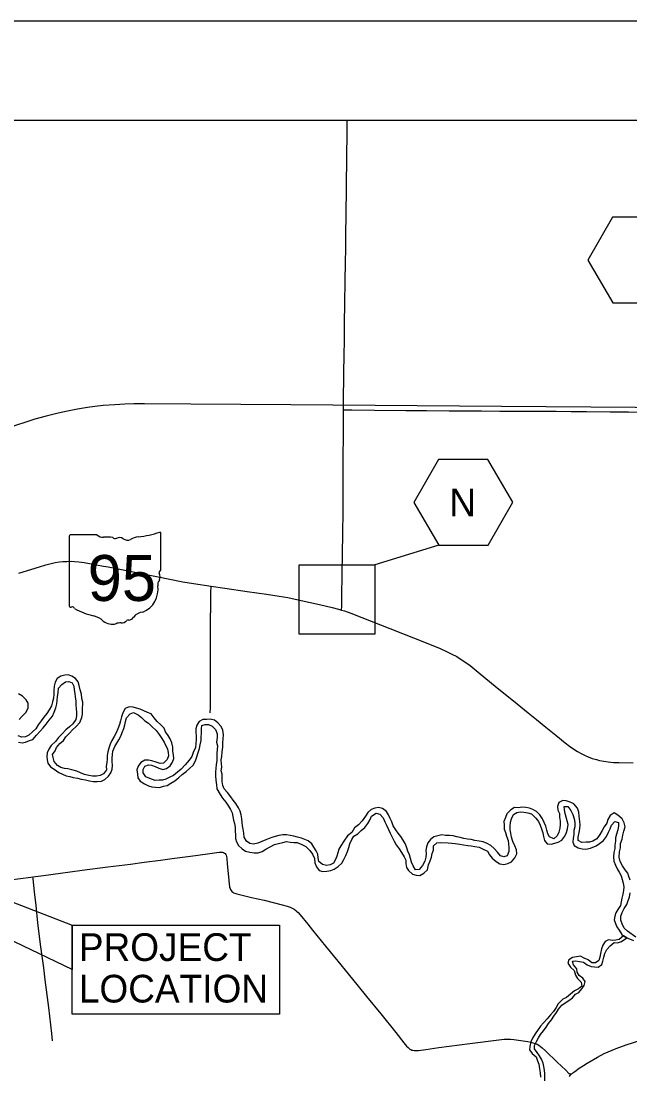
# Model space of a CAD drawing. Extents: x 0 to 680, y 0 to 440.
# Drawn here: x 128.6 to 190.2, y 333.5 to 440 of the extents above; entities that cross this region are included whole.
import ezdxf

# ---------------------------------------------------------------- set-up
doc = ezdxf.new("R2010")
doc.units = 0
for name, color, linetype in [('GM_X_County_Road', 7, 'Continuous'), ('GM_X_Major_River', 7, 'Continuous'), ('GM_X_Minor_River', 7, 'Continuous'), ('GM_X_State_Location', 7, 'Continuous'), ('GM_X_State_Route', 7, 'Continuous'), ('GM_X_State_Shield', 7, 'Continuous'), ('GM_X_Township_Road', 7, 'Continuous'), ('RD_X_RR_2', 7, 'Continuous'), ('SH_Border', 7, 'Continuous'), ('SH_Cut_Line', 7, 'Continuous'), ('SH_Text', 7, 'Continuous')]:
    doc.layers.add(name, color=color, linetype=linetype)

msp = doc.modelspace()

# ---------------------------------------------------------------- linework, layer by layer
at = {"layer": 'GM_X_County_Road'}
msp.add_line((161.21, 400.69), (161.22, 401.21), dxfattribs=at)
for points in [[(161.22, 401.21), (161.25, 404.67), (161.27, 405.98), (161.3, 407.95), (161.32, 409.48), (161.36, 411.45), (161.39, 413.74), (161.42, 415.6), (161.44, 417.02), (161.45, 418.34), (161.48, 420.52), (161.52, 423.04), (161.52, 424.02), (161.54, 425.55), (161.56, 426.43), (161.58, 428.51), (161.59, 430)], [(161.02, 380.47), (161.03, 380.85), (161.03, 381.73), (161.08, 384.24), (161.12, 386.09), (161.15, 388.27), (161.17, 390.35), (161.18, 391.55), (161.19, 396.13), (161.2, 397.88), (161.2, 399.41), (161.21, 400.39), (161.21, 400.69)], [(161.21, 400.69), (161.5, 400.69), (162.04, 400.7), (164.34, 400.67), (167.51, 400.65), (169.59, 400.64), (171.88, 400.62), (175.16, 400.6), (177.02, 400.58), (178.55, 400.57), (180.08, 400.57), (181.83, 400.56), (182.71, 400.56), (184.24, 400.53), (185.77, 400.53), (188.17, 400.5), (190.03, 400.49), (192.11, 400.48)], [(129.78, 353.5), (130.87, 353.65), (132.6, 353.88), (133.58, 354.01), (134.77, 354.17), (137.37, 354.5), (139.65, 354.79), (141.06, 354.98), (142.69, 355.19), (144.1, 355.39), (145.72, 355.6), (147.46, 355.84), (148.65, 355.98), (148.87, 355.99), (148.97, 355.98), (149.07, 355.96), (149.16, 355.91), (149.24, 355.85), (149.3, 355.77), (149.34, 355.68), (149.36, 355.57), (149.4, 355.36), (149.45, 354.82), (149.58, 353.51), (149.64, 352.75), (149.67, 352.52), (149.69, 352.41), (149.73, 352.31), (149.78, 352.21), (149.84, 352.11), (149.92, 352.03), (150.01, 351.96), (150.1, 351.9), (150.21, 351.86), (150.31, 351.82), (150.42, 351.79), (151.91, 351.43), (153.19, 351.14), (154.99, 350.68), (155.52, 350.54), (155.83, 350.43), (156.02, 350.34), (156.21, 350.24), (156.38, 350.11), (156.47, 350.04), (156.62, 349.89), (156.84, 349.65), (157.59, 348.71), (158.07, 348.11), (159.39, 346.51), (160.63, 344.98), (161.67, 343.71), (162.7, 342.44), (163.53, 341.42), (164.99, 339.64), (166.5, 337.77), (167.32, 336.74), (167.59, 336.4), (167.75, 336.24), (167.83, 336.17), (167.92, 336.1), (168.02, 336.05), (168.12, 336), (168.23, 335.97), (168.34, 335.95), (168.45, 335.94), (168.56, 335.94), (168.78, 335.96), (169.55, 336.06), (170.85, 336.25), (173.99, 336.66), (176.92, 337.04), (177.46, 337.09), (177.79, 337.1), (178.11, 337.09), (178.44, 337.05), (179.84, 336.85), (180.16, 336.79), (180.37, 336.74), (180.58, 336.67), (180.78, 336.58), (180.97, 336.48), (181.14, 336.36), (181.31, 336.22), (181.63, 335.93), (182.81, 334.78), (183.68, 333.95), (184, 333.64), (184.04, 333.62), (184.07, 333.6), (184.1, 333.58), (184.16, 333.57), (184.22, 333.58)], [(109.86, 350.92), (123.93, 352.74), (125.34, 352.93), (126.42, 353.06), (129.57, 353.47), (129.78, 353.5)], [(184.22, 333.58), (184.26, 333.59), (184.3, 333.6), (184.32, 333.62), (184.42, 333.68), (184.59, 333.82), (185.03, 334.15), (185.49, 334.45), (185.86, 334.68), (186.91, 335.27), (187.58, 335.63), (187.97, 335.83), (188.37, 336), (188.78, 336.15), (189.81, 336.51), (190.54, 336.75), (191.26, 336.99), (192.62, 337.43), (193.86, 337.84), (195.52, 338.39), (198.12, 339.25), (199.99, 339.87), (203.1, 340.9), (204.77, 341.45)], [(184.05, 333.31), (184.22, 333.58)]]:
    msp.add_lwpolyline(points, dxfattribs=at)
at = {"layer": 'GM_X_Major_River'}
for points in [[(134.83, 371.15), (134.76, 371.54), (134.71, 371.95), (134.59, 372.42), (134.48, 372.84), (134.36, 373.2), (134.1, 373.56), (133.73, 373.8), (133.35, 373.92), (133.01, 373.88), (132.63, 373.79), (132.25, 373.55), (132.05, 373.19), (131.93, 372.79), (131.9, 372.32), (131.92, 371.95), (131.89, 371.57), (131.79, 371.19), (131.67, 370.8), (131.44, 370.39), (131.2, 370.02), (130.91, 369.63), (130.62, 369.27), (130.34, 368.86), (130.1, 368.46), (129.75, 368.15), (129.37, 367.82), (129.03, 367.66), (128.67, 367.62), (128.3, 367.74)], [(128.33, 367.1), (128.7, 367.06), (129.05, 367.12), (129.44, 367.3), (129.79, 367.4), (130.16, 367.82), (130.53, 368.23), (130.82, 368.58), (131.15, 368.94), (131.45, 369.35), (131.76, 369.73), (131.96, 370.16), (132.13, 370.57), (132.21, 370.98), (132.26, 371.33), (132.28, 371.73), (132.34, 372.11), (132.37, 372.57), (132.71, 372.95), (133.09, 373.22), (133.42, 373.26), (133.77, 373.12), (133.92, 372.78), (133.96, 372.4), (134.02, 372.03), (134.07, 371.7), (134.13, 371.26), (134.15, 370.87), (134.18, 370.52), (134.2, 370.11), (134.19, 369.76), (134.15, 369.4), (133.85, 368.96), (133.5, 368.65), (133.12, 368.36), (132.75, 367.96), (132.38, 367.58), (132.08, 367.17), (131.65, 366.79), (131.39, 366.42), (131.25, 366.02), (131.2, 365.68), (131.23, 365.33), (131.31, 364.98), (131.57, 364.63), (131.93, 364.37), (132.42, 364.05), (132.78, 363.87), (133.16, 363.72), (133.53, 363.65), (133.88, 363.56), (134.31, 363.47), (134.68, 363.36), (135.12, 363.3), (135.53, 363.2), (135.89, 363.14), (136.3, 363.13)], [(128.41, 369.4), (128.72, 369.75), (129.11, 370.15), (129.3, 370.57), (129.3, 371.07), (129.11, 371.41), (128.75, 371.76), (128.33, 372.01)], [(147.71, 369.43), (147.38, 369.39), (146.98, 369.39), (146.61, 369.22), (146.37, 368.84), (146.28, 368.45), (146.29, 368.1), (146.32, 367.75), (146.3, 367.38), (146.28, 366.99), (146.24, 366.57), (146.02, 366.07), (145.88, 365.68), (145.6, 365.31), (145.19, 364.84), (144.8, 364.38), (144.43, 364.07), (144.03, 363.73), (143.64, 363.59), (143.25, 363.37), (142.89, 363.28), (142.55, 363.26), (142.15, 363.24), (141.62, 363.43), (141.21, 363.61), (140.95, 364.01), (140.94, 364.35), (141.12, 364.7), (141.47, 364.81), (141.8, 364.79), (142.17, 364.67), (142.53, 364.5), (142.92, 364.35), (143.32, 364.46), (143.68, 364.72), (143.93, 365.09), (144.04, 365.45), (144.02, 365.83), (143.96, 366.22), (143.94, 366.62), (143.83, 367.05), (143.69, 367.44), (143.48, 367.79), (143.22, 368.17), (143.08, 368.54), (142.72, 368.87), (142.36, 369.22), (142.07, 369.59), (141.75, 369.97), (141.4, 370.12), (141.02, 370.27), (140.63, 370.44), (140.28, 370.55), (139.92, 370.64), (139.52, 370.67), (139.13, 370.51), (138.89, 370.08), (138.77, 369.68), (138.64, 369.26), (138.56, 368.91), (138.37, 368.47), (138.2, 368.07), (138.01, 367.68), (137.78, 367.28), (137.62, 366.91), (137.47, 366.52), (137.37, 366.14), (137.32, 365.76), (137.31, 365.4), (137.27, 365.06), (137.22, 364.68), (137.24, 364.31), (136.93, 363.93), (136.59, 363.76), (136.22, 363.67), (135.83, 363.68), (135.44, 363.74), (135.03, 363.86), (134.62, 364.02), (134.24, 364.17), (133.72, 364.33), (133.33, 364.43), (132.99, 364.46), (132.61, 364.57), (132.27, 364.76), (131.93, 365.17), (131.83, 365.55), (131.77, 365.88), (132.03, 366.23), (132.19, 366.58), (132.52, 366.97), (132.9, 367.29), (133.12, 367.64), (133.5, 368.01), (133.81, 368.37), (134.18, 368.7), (134.54, 369.11), (134.74, 369.6), (134.8, 369.96), (134.82, 370.35), (134.83, 371.15)], [(136.3, 363.13), (136.73, 363.17), (137.07, 363.35), (137.43, 363.68), (137.69, 364.02), (137.8, 364.38), (137.85, 364.77), (137.82, 365.17), (137.82, 365.51), (137.86, 365.86), (137.89, 366.22), (138.07, 366.66), (138.27, 367.02), (138.49, 367.36), (138.7, 367.72), (138.83, 368.1), (138.99, 368.49), (139.08, 368.86), (139.16, 369.22), (139.26, 369.58), (139.63, 369.98), (139.97, 370.1), (140.43, 369.87), (140.77, 369.6), (141.11, 369.28), (141.47, 369.02), (141.84, 368.71), (142.26, 368.29), (142.56, 367.9), (142.83, 367.48), (143.08, 367.13), (143.42, 366.42), (143.49, 366.06), (143.5, 365.73), (143.39, 365.36), (143.01, 364.99), (142.67, 364.95), (142.25, 365.08), (141.82, 365.23), (141.48, 365.31), (141.13, 365.29), (140.7, 365.07), (140.43, 364.68), (140.31, 364.31), (140.39, 363.88), (140.42, 363.52), (140.65, 363.16), (141.08, 362.91), (141.49, 362.71), (141.83, 362.59), (142.21, 362.57), (142.61, 362.53), (143, 362.66), (143.36, 362.75), (143.74, 362.97), (144.14, 363.2), (144.55, 363.55), (144.9, 363.85), (145.3, 364.15), (145.64, 364.46), (145.99, 364.8), (146.24, 365.24), (146.37, 365.63), (146.51, 366.07), (146.66, 366.49), (146.72, 366.86), (146.8, 367.28), (146.8, 367.63), (146.83, 368.03), (146.84, 368.45), (146.87, 368.81), (147.22, 368.9), (147.57, 368.9), (147.91, 368.73), (148.26, 368.4), (148.42, 367.96), (148.43, 367.58), (148.37, 367.1), (148.47, 366.73), (148.42, 366.36), (148.39, 365.99), (148.4, 365.65), (148.39, 365.27), (148.32, 364.83), (148.31, 364.5), (148.27, 364.09), (148.27, 363.7), (148.29, 363.28), (148.35, 362.81), (148.4, 362.41), (148.75, 361.81), (148.96, 361.45), (149.31, 361.06), (149.57, 360.66), (149.78, 360.32), (149.95, 359.97), (150.03, 359.59), (150.1, 359.24), (150.18, 358.88), (150.24, 358.52), (150.25, 358.16)], [(169.61, 356.54), (169.55, 356.18), (169.56, 355.85), (169.52, 355.5), (169.44, 355.1), (169.2, 354.65), (168.86, 354.25), (168.49, 354.21), (168.24, 354.6), (168.09, 355), (167.99, 355.37), (167.87, 355.71), (167.72, 356.11), (167.59, 356.52), (167.44, 356.86), (167.24, 357.21), (167.01, 357.57), (166.75, 357.93), (166.51, 358.26), (166.23, 358.67), (166.09, 359.05), (165.93, 359.4), (165.76, 359.76), (165.56, 360.12), (165.16, 360.4), (164.75, 360.5), (164.39, 360.46), (164.02, 360.31), (163.66, 360.01), (163.44, 359.62), (163.1, 359.18), (162.74, 358.77), (162.32, 358.44), (162.06, 358), (161.62, 357.65), (161.25, 357.11), (160.93, 356.64), (160.75, 356.3), (160.64, 355.93), (160.52, 355.58), (160.4, 355.24), (160.21, 354.88), (159.87, 354.71), (159.5, 354.65), (159.09, 354.75), (158.73, 355.06), (158.63, 355.44), (158.6, 355.8), (158.46, 356.14), (158.22, 356.5), (157.99, 356.85), (157.64, 357.13), (157.3, 357.29), (156.95, 357.41), (156.54, 357.52), (156.2, 357.63), (155.8, 357.68), (155.45, 357.74), (155.08, 357.74), (154.68, 357.68), (154.06, 357.51), (153.68, 357.38), (153.35, 357.24), (152.96, 357.08), (152.54, 356.9), (152.1, 356.82), (151.74, 356.88), (151.4, 357.11), (151.16, 357.5), (151.13, 357.9), (151.07, 358.32), (151.01, 358.67), (150.96, 359.01), (150.93, 359.36), (150.87, 359.77), (150.75, 360.13), (150.6, 360.48), (150.31, 360.9), (150.06, 361.24), (149.8, 361.59), (149.49, 362.03), (149.13, 362.41), (148.99, 362.75), (148.93, 363.13), (148.95, 363.47), (148.93, 363.87), (148.84, 364.22), (148.91, 364.58), (148.88, 364.93), (148.85, 365.32), (148.91, 365.68), (148.95, 366.15), (149.01, 366.6), (149.01, 367.05), (149.03, 367.44), (149.06, 367.87), (149.02, 368.32), (148.85, 368.71), (148.51, 369.07), (148.16, 369.33), (147.71, 369.43)], [(189.95, 353.87), (189.71, 354.21), (189.43, 354.61), (189.19, 355.06), (189.08, 355.5), (189.12, 356.02), (189.24, 356.43), (189.24, 356.87), (189.41, 357.31), (189.45, 357.7), (189.55, 358.11), (189.68, 358.55), (189.61, 358.97), (189.39, 359.37), (188.96, 359.73), (188.57, 359.96), (188.18, 359.7), (187.96, 359.31), (187.83, 358.94), (187.58, 358.57), (187.38, 358.17), (187.12, 357.79), (186.84, 357.35), (186.44, 357.11), (186.1, 357.01), (185.74, 357.01), (185.31, 356.98), (184.93, 357.19), (184.95, 357.52), (185.05, 357.97), (185.11, 358.34), (185.13, 358.75), (185.1, 359.09), (185.05, 359.62), (185, 360.03), (184.86, 360.43), (184.5, 360.88), (184.14, 361.06), (183.73, 361.2), (183.38, 361.23), (182.99, 361.01), (182.85, 360.61), (182.9, 360.23), (183.04, 359.89), (183.05, 359.54), (183.12, 359.13), (183.11, 358.78), (183.1, 358.42), (182.98, 358.03), (182.83, 357.65), (182.49, 357.36), (182.05, 357.53), (181.88, 357.86), (181.78, 358.21), (181.66, 358.63), (181.49, 358.98), (181.32, 359.38), (181.06, 359.77), (180.72, 360.11), (180.36, 360.31), (180.02, 360.45), (179.66, 360.51), (179.27, 360.55), (178.88, 360.48), (178.51, 360.51), (178.13, 360.28), (177.73, 359.86), (177.61, 359.51), (177.42, 359.1), (177.45, 358.71), (177.46, 358.32), (177.59, 357.99), (177.68, 357.61), (177.86, 357.18), (177.9, 356.85), (177.92, 356.44), (177.94, 356.07), (177.76, 355.63), (177.43, 355.52), (177.08, 355.62), (176.8, 356.01), (176.45, 356.36), (176.1, 356.68), (175.74, 356.88), (175.32, 357.04), (174.93, 357.12), (174.5, 357.17), (174.11, 357.27), (173.76, 357.3), (173.39, 357.38), (173.01, 357.47), (172.67, 357.56), (172.31, 357.66), (171.94, 357.68), (171.54, 357.69), (171.14, 357.76), (170.75, 357.65), (170.36, 357.55), (170.01, 357.28), (169.74, 356.94), (169.61, 356.54)], [(178.21, 357.51), (178.13, 357.9), (178.05, 358.26), (178.08, 358.62), (178.11, 359.03), (178.19, 359.38), (178.39, 359.79), (178.73, 360.01), (179.09, 360.06), (179.45, 360.03), (179.85, 359.97), (180.21, 359.87), (180.67, 359.43), (180.94, 359.1), (181.1, 358.71), (181.24, 358.34), (181.38, 357.95), (181.45, 357.58), (181.53, 357.17), (181.81, 356.84), (182.21, 356.82), (182.59, 356.89), (182.93, 357), (183.29, 357.21), (183.58, 357.63), (183.78, 357.99), (183.86, 358.35), (183.93, 358.79), (183.84, 359.18), (183.74, 359.52), (183.63, 359.91), (183.55, 360.27), (183.53, 360.6), (183.91, 360.62), (184.21, 360.22), (184.41, 359.81), (184.53, 359.38), (184.59, 359), (184.59, 358.55), (184.52, 358.18), (184.5, 357.78), (184.43, 357.42), (184.39, 357.02), (184.55, 356.67), (184.96, 356.44), (185.36, 356.34), (185.73, 356.3), (186.19, 356.4), (186.76, 356.62), (187.1, 356.88), (187.49, 357.18), (187.82, 357.58), (188.01, 358.02), (188.17, 358.37), (188.33, 358.73), (188.65, 359.09), (189.02, 358.98), (189.03, 358.64), (188.95, 358.27), (188.81, 357.82), (188.73, 357.44), (188.71, 357.11), (188.65, 356.72), (188.64, 356.38), (188.54, 355.95), (188.53, 355.52), (188.54, 355.07), (188.72, 354.69), (188.89, 354.31), (189.08, 353.98), (189.28, 353.61), (189.38, 353.25), (189.49, 352.87), (189.57, 352.5), (189.52, 352.11), (189.45, 351.74), (189.37, 351.36), (189.3, 350.99), (189.24, 350.6), (188.96, 350.21), (188.75, 349.86), (188.65, 349.52), (188.58, 349.16), (188.73, 348.79), (188.87, 348.46), (189.08, 348.12), (189.35, 347.68), (189.52, 347.53)], [(150.25, 358.16), (150.28, 357.72), (150.28, 357.37), (150.39, 357.03), (150.6, 356.68), (150.97, 356.33), (151.31, 356.11), (151.72, 355.99), (152.16, 355.93), (152.59, 355.94), (152.99, 356.08), (153.37, 356.3), (153.79, 356.54), (154.23, 356.76), (154.64, 356.87), (155.08, 356.98), (155.43, 357.08), (155.8, 357.02), (156.2, 356.96), (156.53, 356.97), (156.98, 356.76), (157.41, 356.56), (157.8, 356.16), (158.09, 355.8), (158.27, 355.35), (158.3, 354.92), (158.48, 354.52), (158.74, 354.15), (159.12, 354.05), (159.53, 354.07), (159.94, 354.15), (160.28, 354.29), (160.66, 354.54), (161.04, 354.89), (161.23, 355.26), (161.46, 355.65), (161.63, 356.05), (161.76, 356.47), (161.86, 356.83), (162.05, 357.27), (162.26, 357.61), (162.66, 357.85), (163.01, 358.17), (163.35, 358.5), (163.67, 358.9), (163.89, 359.3), (164.05, 359.64), (164.5, 359.93), (164.88, 359.85), (165.22, 359.46), (165.38, 359.06), (165.55, 358.71), (165.77, 358.28), (165.92, 357.9), (166.14, 357.51), (166.35, 357.12), (166.54, 356.73), (166.83, 356.35), (167.08, 355.97), (167.34, 355.54), (167.5, 355.19), (167.51, 354.84), (167.57, 354.46), (167.77, 354.13), (168.2, 353.78), (168.57, 353.68), (168.93, 353.65), (169.34, 353.86), (169.69, 354.2), (169.82, 354.71), (169.96, 355.13), (170.1, 355.5), (170.17, 355.85), (170.3, 356.21), (170.32, 356.64), (170.66, 356.93), (171, 356.96), (171.79, 356.95), (172.15, 356.9), (172.51, 356.87), (172.98, 356.81), (173.35, 356.73), (173.78, 356.67), (174.12, 356.64), (174.48, 356.58), (174.92, 356.49), (175.27, 356.34), (175.77, 356.11), (175.99, 355.74), (176.25, 355.39), (176.65, 355.04), (177.03, 354.82), (177.44, 354.76), (177.83, 354.84), (178.19, 355.01), (178.55, 355.41), (178.74, 355.84), (178.71, 356.22), (178.55, 356.62), (178.35, 357.07), (178.21, 357.51)], [(190.19, 353.18), (190.08, 353.52), (189.95, 353.87)], [(190.78, 347.42), (189.93, 348.01), (189.58, 348.33), (189.4, 348.74), (189.27, 349.12), (189.25, 349.53), (189.39, 349.91), (189.6, 350.29), (189.86, 350.69), (190.01, 351.1), (190.12, 351.46), (190.2, 351.9)], [(189.52, 347.53), (189.85, 347.35)], [(189.85, 347.35), (190.15, 347.22), (190.53, 347.08)]]:
    msp.add_lwpolyline(points, dxfattribs=at)
at = {"layer": 'GM_X_Minor_River'}
for points in [[(189.52, 347.53), (189.09, 347.18), (188.74, 347.1), (188.41, 347.08), (188.01, 347.12), (187.67, 346.97), (187.45, 346.6), (187.3, 346.21), (187.2, 345.76), (187.14, 345.4), (187.03, 345.03), (186.68, 344.81), (186.32, 344.82), (185.95, 345.1), (185.56, 345.28), (185.17, 345.48), (184.78, 345.42), (184.36, 345.36), (184.01, 345.12), (183.89, 344.77), (184.17, 344.37), (184.53, 344.04), (184.68, 343.57), (184.86, 343.23), (185.23, 342.86), (185.31, 342.46), (184.97, 342.17), (184.58, 341.99), (184.18, 341.65), (183.75, 341.32), (183.4, 341.14), (182.93, 340.68), (182.71, 340.3), (182.46, 339.9), (182.13, 339.56), (181.82, 339.15), (181.45, 338.76), (181.14, 338.41), (180.89, 338.06), (180.58, 337.65), (180.33, 337.2), (180.17, 336.84), (180.07, 336.37), (180.01, 336.01), (180.29, 335.63), (180.68, 335.31), (180.84, 334.92), (180.96, 334.57), (181.02, 334.08), (181.1, 333.7), (181.14, 333.25)], [(181.56, 332.89), (181.57, 333.59), (181.54, 333.96), (181.46, 334.33), (181.41, 334.67), (181.25, 335.07), (181.03, 335.42), (180.8, 335.76), (180.52, 336.12), (180.51, 336.46), (180.72, 336.86), (180.93, 337.23), (181.13, 337.57), (181.44, 337.93), (181.71, 338.31), (181.95, 338.67), (182.25, 339.04), (182.48, 339.43), (182.75, 339.78), (182.96, 340.12), (183.28, 340.52), (183.64, 340.78), (184.01, 341), (184.36, 341.26), (184.68, 341.63), (185.01, 341.82), (185.31, 342.17), (185.56, 342.52), (185.65, 342.92), (185.4, 343.26), (185.06, 343.52), (184.85, 343.86), (184.81, 344.22), (184.47, 344.61), (184.36, 344.98), (184.71, 345.01), (185.07, 344.95), (185.48, 344.87), (185.85, 344.6), (186.25, 344.45), (186.61, 344.42), (186.98, 344.37), (187.33, 344.65), (187.44, 344.99), (187.53, 345.37), (187.65, 345.76), (187.83, 346.15), (188.17, 346.53), (188.57, 346.85), (188.93, 346.83), (189.32, 346.97), (189.85, 347.35)], [(189.85, 347.35), (189.52, 347.53)]]:
    msp.add_lwpolyline(points, dxfattribs=at)
at = {"layer": 'GM_X_State_Route'}
msp.add_line((170.84, 387.01), (164.37, 385.03), dxfattribs=at)
for points in [[(193.42, 420.19), (188.42, 420.17), (185.93, 415.83), (188.44, 411.51), (193.44, 411.53), (195.93, 415.86)], [(175.81, 395.69), (170.81, 395.67), (168.32, 391.33), (170.84, 387.01), (175.84, 387.03), (178.32, 391.37)]]:
    msp.add_lwpolyline(points, close=True, dxfattribs=at)
msp.add_lwpolyline([(128.38, 384.18), (130.47, 384.84), (131.1, 385.03), (131.63, 385.17), (132.05, 385.26), (132.48, 385.33), (132.81, 385.37), (133.24, 385.39), (133.68, 385.4), (134.01, 385.38), (134.44, 385.35), (134.98, 385.28), (135.52, 385.19), (136.92, 384.92), (137.4, 384.82), (140.78, 384.15), (143.46, 383.61), (144.97, 383.33), (146.05, 383.16), (147.81, 382.88), (149.19, 382.67), (151.46, 382.35), (153.41, 382.07), (154.71, 381.88), (155.57, 381.73), (156.64, 381.51), (158.78, 381.03), (160.06, 380.73), (160.69, 380.57), (161.02, 380.47), (161.32, 380.38), (161.94, 380.17), (163.06, 379.73), (165.91, 378.6), (169.57, 377.14), (170.99, 376.57), (171.69, 376.26), (172.18, 376.02), (172.66, 375.76), (173.12, 375.48), (173.58, 375.17), (174.01, 374.85), (175.04, 374.03), (176.56, 372.78), (178.77, 370.99), (179.88, 370.09), (180.73, 369.4), (181.66, 368.64), (182.68, 367.81), (183.62, 367.05), (184.05, 366.72), (184.5, 366.41), (184.87, 366.18), (185.26, 365.96), (185.65, 365.77), (185.95, 365.64), (186.37, 365.48), (186.79, 365.35), (187.11, 365.27), (187.54, 365.19), (187.97, 365.13), (188.52, 365.07), (189.07, 365.05), (190.49, 365.02)], dxfattribs=at)
at = {"layer": 'GM_X_State_Shield'}
for p, q in [((133.46, 387.94), (133.46, 380.89)), ((136.27, 388.06), (133.55, 388.06)), ((142.74, 384.55), (142.74, 388.23)), ((142.74, 384.55), (142.74, 384.55))]:
    msp.add_line(p, q, dxfattribs=at)
for centre, radius, start, end in [((133.57, 387.95), 0.108, 98.1301, 188.1301), ((136.92, 388.87), 1.04, 231.6195, 271.1119), ((137.26, 384.1), 3.74, 80.4867, 94.9883), ((138.11, 387.99), 0.301, 219.7921, 297.1024), ((138.55, 387.17), 0.626, 54.4667, 119.1411), ((140.69, 385.91), 1.98, 97.3462, 120.7689), ((139.44, 397.66), 9.84, 275.8445, 288.9065), ((142.64, 388.25), 0.103, 351.8621, 97.738), ((139.36, 388.29), 0.753, 233.8562, 294.8282), ((142.63, 384.53), 0.111, 289.6038, 7.7341), ((143.11, 383), 0.698, 136.8065, 186.9296), ((142.72, 384.28), 0.16, 107.944, 210.337), ((141.7, 383.81), 0.96, 340.033, 23.6496), ((139.99, 382.54), 2.46, 292.3089, 8.9858), ((133.57, 380.88), 0.108, 171.9584, 258.3066), ((133.58, 381.6), 0.828, 267.339, 280.6039), ((133.75, 380.49), 0.298, 29.7484, 93.2717), ((137.52, 386.81), 7.11, 240.4129, 257.1985), ((135.4, 377.73), 2.22, 47.1842, 75.836), ((137.81, 380.45), 1.41, 230.7004, 286.2918), ((138.73, 379.92), 0.752, 268.777, 315.5493), ((139.41, 379.24), 0.212, 65.7517, 132.6484), ((139.32, 380.21), 0.795, 282.8732, 323.2771), ((141.03, 378.91), 1.35, 94.4031, 142.5768), ((138.62, 378.01), 1.16, 85.6951, 111.2099)]:
    msp.add_arc(centre, radius, start, end, dxfattribs=at)
at = {"layer": 'GM_X_Township_Road'}
for points in [[(147.74, 370.08), (147.75, 370.62), (147.75, 371.39), (147.75, 372.71), (147.75, 373.48), (147.75, 374.57), (147.75, 375.34), (147.75, 376), (147.76, 376.87), (147.77, 378.08), (147.77, 378.52), (147.77, 378.95), (147.77, 379.28), (147.77, 379.5), (147.77, 379.72), (147.77, 380.16), (147.78, 380.27), (147.78, 380.49), (147.79, 380.6), (147.79, 380.71), (147.79, 380.82), (147.78, 381.14), (147.79, 381.8), (147.79, 382.35), (147.81, 382.74), (147.81, 382.88)], [(131.77, 336.91), (131.7, 337.67), (131.4, 340.28), (131.05, 343.1), (130.89, 344.29), (130.57, 346.68), (130.29, 348.85), (130.11, 350.59), (129.97, 352), (129.81, 353.3), (129.78, 353.5)]]:
    msp.add_lwpolyline(points, dxfattribs=at)
at = {"layer": 'RD_X_RR_2'}
msp.add_lwpolyline([(199.79, 400.86), (177.18, 401.05), (155.89, 401.21), (145.78, 401.29), (141.07, 401.32), (139.99, 401.32), (139.09, 401.28), (138.07, 401.22), (136.91, 401.13), (136.06, 401.04), (135.32, 400.93), (134.31, 400.77), (133.28, 400.58), (132.35, 400.38), (131.12, 400.08), (129.99, 399.76), (129.07, 399.46), (128.04, 399.12), (127.16, 398.8), (125.42, 398.09), (104.89, 389.72), (80.55, 379.82), (63.35, 372.77), (30, 359.11)], dxfattribs=at)
at = {"layer": 'SH_Border'}
for points in [[(30, 430), (670, 430), (670, 10), (30, 10)], [(156.74, 385.03), (164.37, 385.03), (164.37, 378.03), (156.74, 378.03)]]:
    msp.add_lwpolyline(points, close=True, dxfattribs=at)
at = {"layer": 'SH_Cut_Line'}
msp.add_lwpolyline([(0, 0), (680, 0), (680, 440), (0, 440)], close=True, dxfattribs=at)
at = {"layer": 'SH_Text'}
for points in [[(30, 430), (466.92, 430), (466.92, 291.27), (342.9, 138.72), (30, 138.72)], [(133.77, 344.12), (84.83, 367.6), (133.77, 348.61)], [(133.77, 348.61), (154.75, 348.61), (154.75, 339.62), (133.77, 339.62)]]:
    msp.add_lwpolyline(points, close=True, dxfattribs=at)

# ---------------------------------------------------------------- texts
at = {"layer": 'GM_X_State_Location'}
for s in ['s', 'r']:
    msp.add_text(s, height=0.00667, dxfattribs=at).set_placement((138, 383.95))
msp.add_text('95', height=0.00667, rotation=0, dxfattribs=at).set_placement((136.32, 383.46))
at = {"layer": 'GM_X_State_Route'}
msp.add_text('N', height=2.8, dxfattribs=at).set_placement((171.91, 389.95))
at = {"layer": 'GM_X_State_Shield'}
msp.add_text('95', height=4.641, dxfattribs=at).set_placement((135.34, 381.39))
at = {"layer": 'SH_Text'}
for s, p in [('PROJECT', (134.44, 345)), ('LOCATION', (134.44, 340.8))]:
    msp.add_text(s, height=2.8, dxfattribs=at).set_placement(p)

doc.saveas('drawing.dxf')
